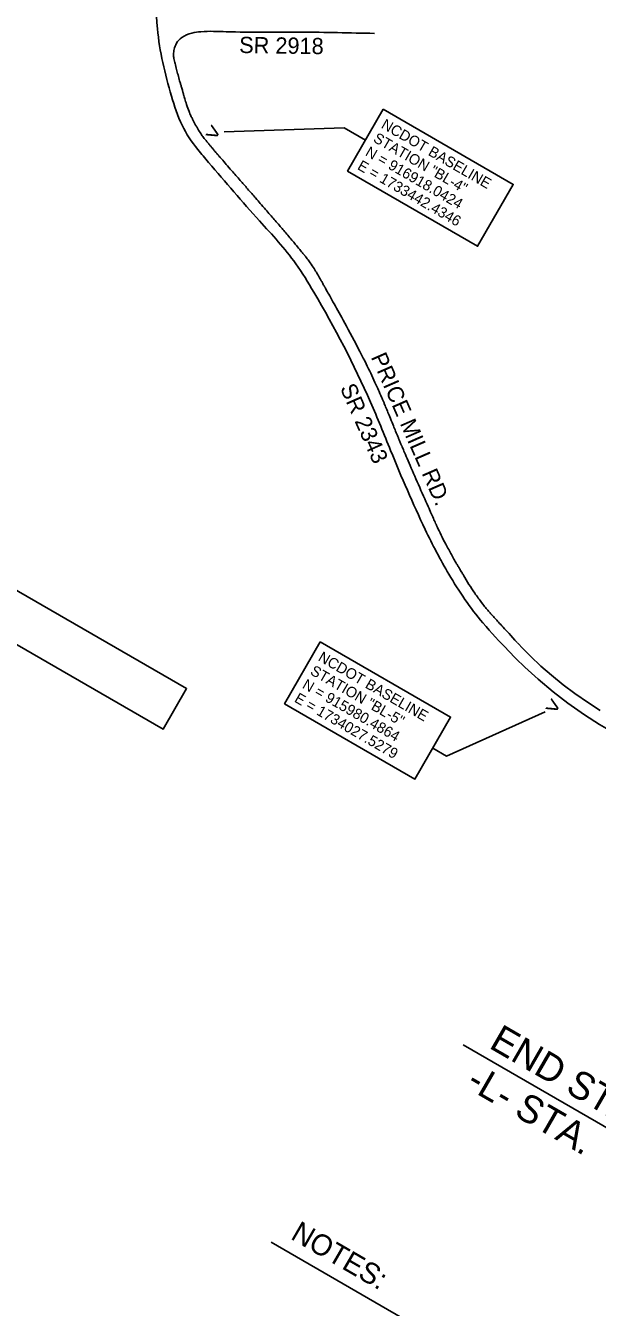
# Model space of a CAD drawing. Extents: x 1729269 to 1736953, y 913137 to 919486.
# Drawn here: x 1733139 to 1734090, y 914972 to 917102 of the extents above; entities that cross this region are included whole.
import ezdxf

# ---------------------------------------------------------------- set-up
doc = ezdxf.new("R2010")
doc.units = 0
for name, color, linetype in [('CTL Sheet Border CELL', 7, 'Continuous'), ('CTL Sheet Notes CELL', 7, 'Continuous'), ('CTL Sheet Text', 7, 'Continuous'), ('Default', 7, 'Continuous'), ('Exist Roads EOP', 7, 'Continuous'), ('Old_Level_57', 7, 'Continuous'), ('Proposed Right of Way Monument PSD Text', 7, 'Continuous')]:
    doc.layers.add(name, color=color, linetype=linetype)

msp = doc.modelspace()

# ---------------------------------------------------------------- linework, layer by layer
at = {"layer": 'CTL Sheet Border CELL'}
msp.add_lwpolyline([(1730899.3, 917447.9), (1733406.5, 916000.4), (1733367.6, 915933), (1730860.5, 917380.5)], close=True, dxfattribs=at)
at = {"layer": 'CTL Sheet Notes CELL'}
msp.add_line((1733546.9, 915080.5), (1735135.7, 914163.2), dxfattribs=at)
at = {"layer": 'CTL Sheet Text'}
msp.add_line((1734764.2, 914889.5), (1733866.3, 915408), dxfattribs=at)
at = {"layer": 'Default'}
for points in [[(1733733.5, 916963.3), (1733949.8, 916838.4), (1733890.4, 916735.5), (1733674.1, 916860.4)], [(1733628.7, 916078.1), (1733845.5, 915952.9), (1733786.1, 915850), (1733569.3, 915975.2)]]:
    msp.add_lwpolyline(points, close=True, dxfattribs=at)
for points in [[(1733703.8, 916911.9), (1733668.5, 916932.2), (1733469.1, 916925.6)], [(1733815.8, 915901.4), (1733838.7, 915888.2), (1734002.8, 915961.9)]]:
    msp.add_lwpolyline(points, dxfattribs=at)
at = {"layer": 'Exist Roads EOP'}
for points in [[(1734094.4, 915963.9), (1734074.8, 915976.6), (1734052.1, 915992.3), (1734032.8, 916006.6), (1734013.4, 916022.6), (1733995.8, 916037.8), (1733978.4, 916054.2), (1733966.2, 916066.6), (1733956.6, 916076.5)], [(1734357.9, 915844.5), (1734311, 915854.6), (1734275.3, 915863.4), (1734247.5, 915872), (1734217.2, 915881.5), (1734189.8, 915891.8), (1734164.5, 915903.1), (1734143.9, 915913), (1734120.1, 915925.3), (1734093.2, 915940.8), (1734068, 915956.5), (1734040.6, 915976.2), (1734015.8, 915995.2), (1733991.1, 916015.8), (1733969, 916035.9), (1733954, 916050.6), (1733941.6, 916063.3)]]:
    msp.add_lwpolyline(points, dxfattribs=at)
for points in [[(1733941.6, 916063.3), (1733899.3, 916109.4), (1733842.6, 916190.4), (1733803.3, 916264.8), (1733745.8, 916396.1), (1733712.4, 916476.4), (1733618, 916659.4), (1733588.1, 916706.6), (1733527.8, 916777.7), (1733443.1, 916874.9), (1733425, 916896.5), (1733399, 916936.6), (1733381.3, 916985.3), (1733357.9, 917097.2), (1733355.4, 917180.6), (1733347.7, 917440.6)], [(1733718.8, 917089.3), (1733596.5, 917091.4), (1733472.4, 917092.2), (1733430.2, 917092.2), (1733415.4, 917090), (1733398.5, 917082.4), (1733389.8, 917073), (1733385.8, 917062.9), (1733384.8, 917054.3), (1733385.2, 917047.8)]]:
    msp.add_spline(points, degree=3, dxfattribs=at)
msp.add_open_spline([(1733956.3, 916076.8), (1733945.4, 916088.7), (1733931.8, 916103.5), (1733917.9, 916118.7), (1733914.7, 916122.1), (1733914.3, 916122.6), (1733914.1, 916122.8), (1733914, 916122.9), (1733913.8, 916123.1), (1733913, 916124), (1733911, 916126.2), (1733909.1, 916128.4), (1733903.1, 916135.5), (1733898.4, 916141.4), (1733884.8, 916159.8), (1733876.4, 916173), (1733866.1, 916189.9), (1733864.1, 916193.3), (1733861.1, 916198.4), (1733860, 916200.2), (1733858, 916203.6), (1733857, 916205.3), (1733852, 916213.9), (1733848.1, 916220.8), (1733836.7, 916241.5), (1733829.6, 916255.3), (1733822.7, 916270.3), (1733822.2, 916271.4), (1733821.7, 916272.5), (1733821.6, 916272.8), (1733821.5, 916272.9), (1733821.4, 916273.2), (1733821.2, 916273.7), (1733820.1, 916276.1), (1733817.4, 916282.1), (1733811.7, 916294.9), (1733793.8, 916335.3), (1733777.8, 916372.1), (1733765, 916402.1), (1733764.7, 916402.8), (1733764.4, 916403.5), (1733764.2, 916403.9), (1733764.1, 916404.2), (1733763.6, 916405.3), (1733762.4, 916408), (1733761.3, 916410.8), (1733759, 916416.3), (1733757.4, 916420), (1733752.9, 916431), (1733749.8, 916438.5), (1733743.7, 916453.4), (1733740.7, 916460.9), (1733736, 916472.2), (1733734.4, 916475.9), (1733732, 916481.6), (1733731.2, 916483.5), (1733729.5, 916487.2), (1733728.7, 916489.1), (1733714.6, 916521), (1733700.1, 916550.2), (1733669.7, 916607.7), (1733654, 916636), (1733637.7, 916665.1), (1733637.2, 916666), (1733636.2, 916667.7), (1733635.7, 916668.6), (1733634.3, 916671.3), (1733633.3, 916673), (1733630.3, 916678.4), (1733628.3, 916682), (1733622, 916692.8), (1733617.5, 916700.2), (1733609.9, 916711.1), (1733607.3, 916714.7), (1733604.2, 916718.4), (1733604, 916718.8), (1733603.7, 916719.1), (1733603.6, 916719.3), (1733603.5, 916719.3), (1733603.4, 916719.4), (1733603.1, 916719.9), (1733602.1, 916721.1), (1733599.8, 916723.9), (1733592.7, 916732.5), (1733586.2, 916740.3), (1733570.5, 916758.9), (1733560, 916771.2), (1733544.1, 916789.5), (1733538.8, 916795.6), (1733528.2, 916807.7), (1733522.9, 916813.8), (1733507, 916832), (1733496.4, 916844.1), (1733480.6, 916862.3), (1733472.6, 916871.4), (1733464.1, 916881.3), (1733460.5, 916885.4), (1733459.3, 916886.8), (1733458.7, 916887.4), (1733458.4, 916887.7), (1733458.3, 916887.9), (1733458.2, 916888), (1733458.2, 916888), (1733456.9, 916889.5), (1733455.6, 916891), (1733451.8, 916895.5), (1733449.3, 916898.5), (1733445.5, 916903.1), (1733444.2, 916904.6), (1733442.3, 916906.9), (1733441.5, 916907.9), (1733440.7, 916908.9), (1733440.5, 916909.1), (1733440.5, 916909.2), (1733440.4, 916909.2), (1733440.4, 916909.3), (1733440.3, 916909.4), (1733439.9, 916909.9), (1733439.6, 916910.3), (1733434.7, 916916.3), (1733430.5, 916922.3), (1733424.7, 916931.5), (1733422.8, 916934.7), (1733420.1, 916939.5), (1733419.2, 916941.2), (1733417.9, 916943.6), (1733417.4, 916944.6), (1733416.9, 916945.5), (1733416.8, 916945.7), (1733416.8, 916945.7), (1733416.8, 916945.8), (1733416.6, 916946.1), (1733416.3, 916946.7), (1733416, 916947.3), (1733412.7, 916954.2), (1733410, 916960.9), (1733405.1, 916974.9), (1733403, 916982.2), (1733400.8, 916990), (1733400.7, 916990.2), (1733400.6, 916990.7), (1733400.5, 916991), (1733400.3, 916991.7), (1733399.9, 916993.2), (1733398.9, 916996.7), (1733398.1, 916999.6), (1733396.4, 917005.5), (1733395.3, 917009.4), (1733392.1, 917021.1), (1733389.9, 917028.7), (1733387, 917040.2), (1733386, 917044), (1733385.2, 917047.8)], degree=3, dxfattribs=at)

# ---------------------------------------------------------------- texts
at = {"layer": 'CTL Sheet Notes CELL'}
msp.add_text('NOTES:', height=34.78, rotation=329.8948, dxfattribs=at).set_placement((1733577.8, 915086.6))
at = {"layer": 'CTL Sheet Text'}
for s, height, p in [('END STATE PROJECT ', 45.911, (1733907.6, 915404)), ('-L- STA. ', 45.91, (1733869.4, 915337.7))]:
    msp.add_text(s, height=height, rotation=330, dxfattribs=at).set_placement(p)
at = {"layer": 'Exist Roads EOP'}
for s, rotation, p in [('SR 2918', 359.1492, (1733493.8, 917056.8)), ('PRICE MILL RD.', 293.6638, (1733712.4, 916551.5)), ('SR 2343', 293.8026, (1733661.1, 916500.2))]:
    msp.add_text(s, height=27, rotation=rotation, dxfattribs=at).set_placement(p)
at = {"layer": 'Old_Level_57'}
for p in [(1733434.4, 916918.2), (1733999.6, 915964.7)]:
    msp.add_text('>', height=28.7, rotation=330.0142, dxfattribs=at).set_placement(p)
at = {"layer": 'Proposed Right of Way Monument PSD Text'}
for s, p in [('NCDOT BASELINE', (1733728.7, 916933)), ('STATION "BL-4"', (1733715.5, 916910.2)), ('N = 916918.0424', (1733702.3, 916887.3)), ('E = 1733442.4346', (1733689.1, 916864.4)), ('NCDOT BASELINE', (1733623.9, 916047.8)), ('STATION "BL-5"', (1733610.7, 916024.9)), ('N = 915980.4864', (1733597.5, 916002.1)), ('E = 1734027.5279', (1733584.3, 915979.2))]:
    msp.add_text(s, height=17.6, rotation=330, dxfattribs=at).set_placement(p)

doc.saveas('drawing.dxf')
